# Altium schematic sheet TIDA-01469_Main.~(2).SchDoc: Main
size 431 x 279 mm; Date: Not shown in title block; ApprovedBy: Not shown in title block; CheckedBy: Not shown in title block; Author: Not shown in title block; CompanyName: Not shown in title block; DrawnBy: Nathan Siegel; Engineer: Not shown in title block; Organization: Not shown in title block; Address1: Not shown in title block; Address2: Not shown in title block; Address3: Not shown in title block; Address4: Not shown in title block; DocumentNumber: 2; Revision: Use project parameter SCH_Rev; SheetNumber: 2; SheetTotal: 4; PageSetup: Record=PageOptions¦CenterHorizontal=True¦CenterVertical=True¦PrintScale=1.00¦XCorrection=1.00¦YCorrection=1.00¦PrintKind=0¦BorderSize=5000000¦LeftOffset=0¦BottomOffset=0¦Orientation=2¦PaperLength=1000¦PaperWidth=1000¦Scale=100¦PaperSource=15¦PrintQuality=600¦MediaType=1¦DitherType=10¦PaperKind=Letter¦PrintScaleMode=1
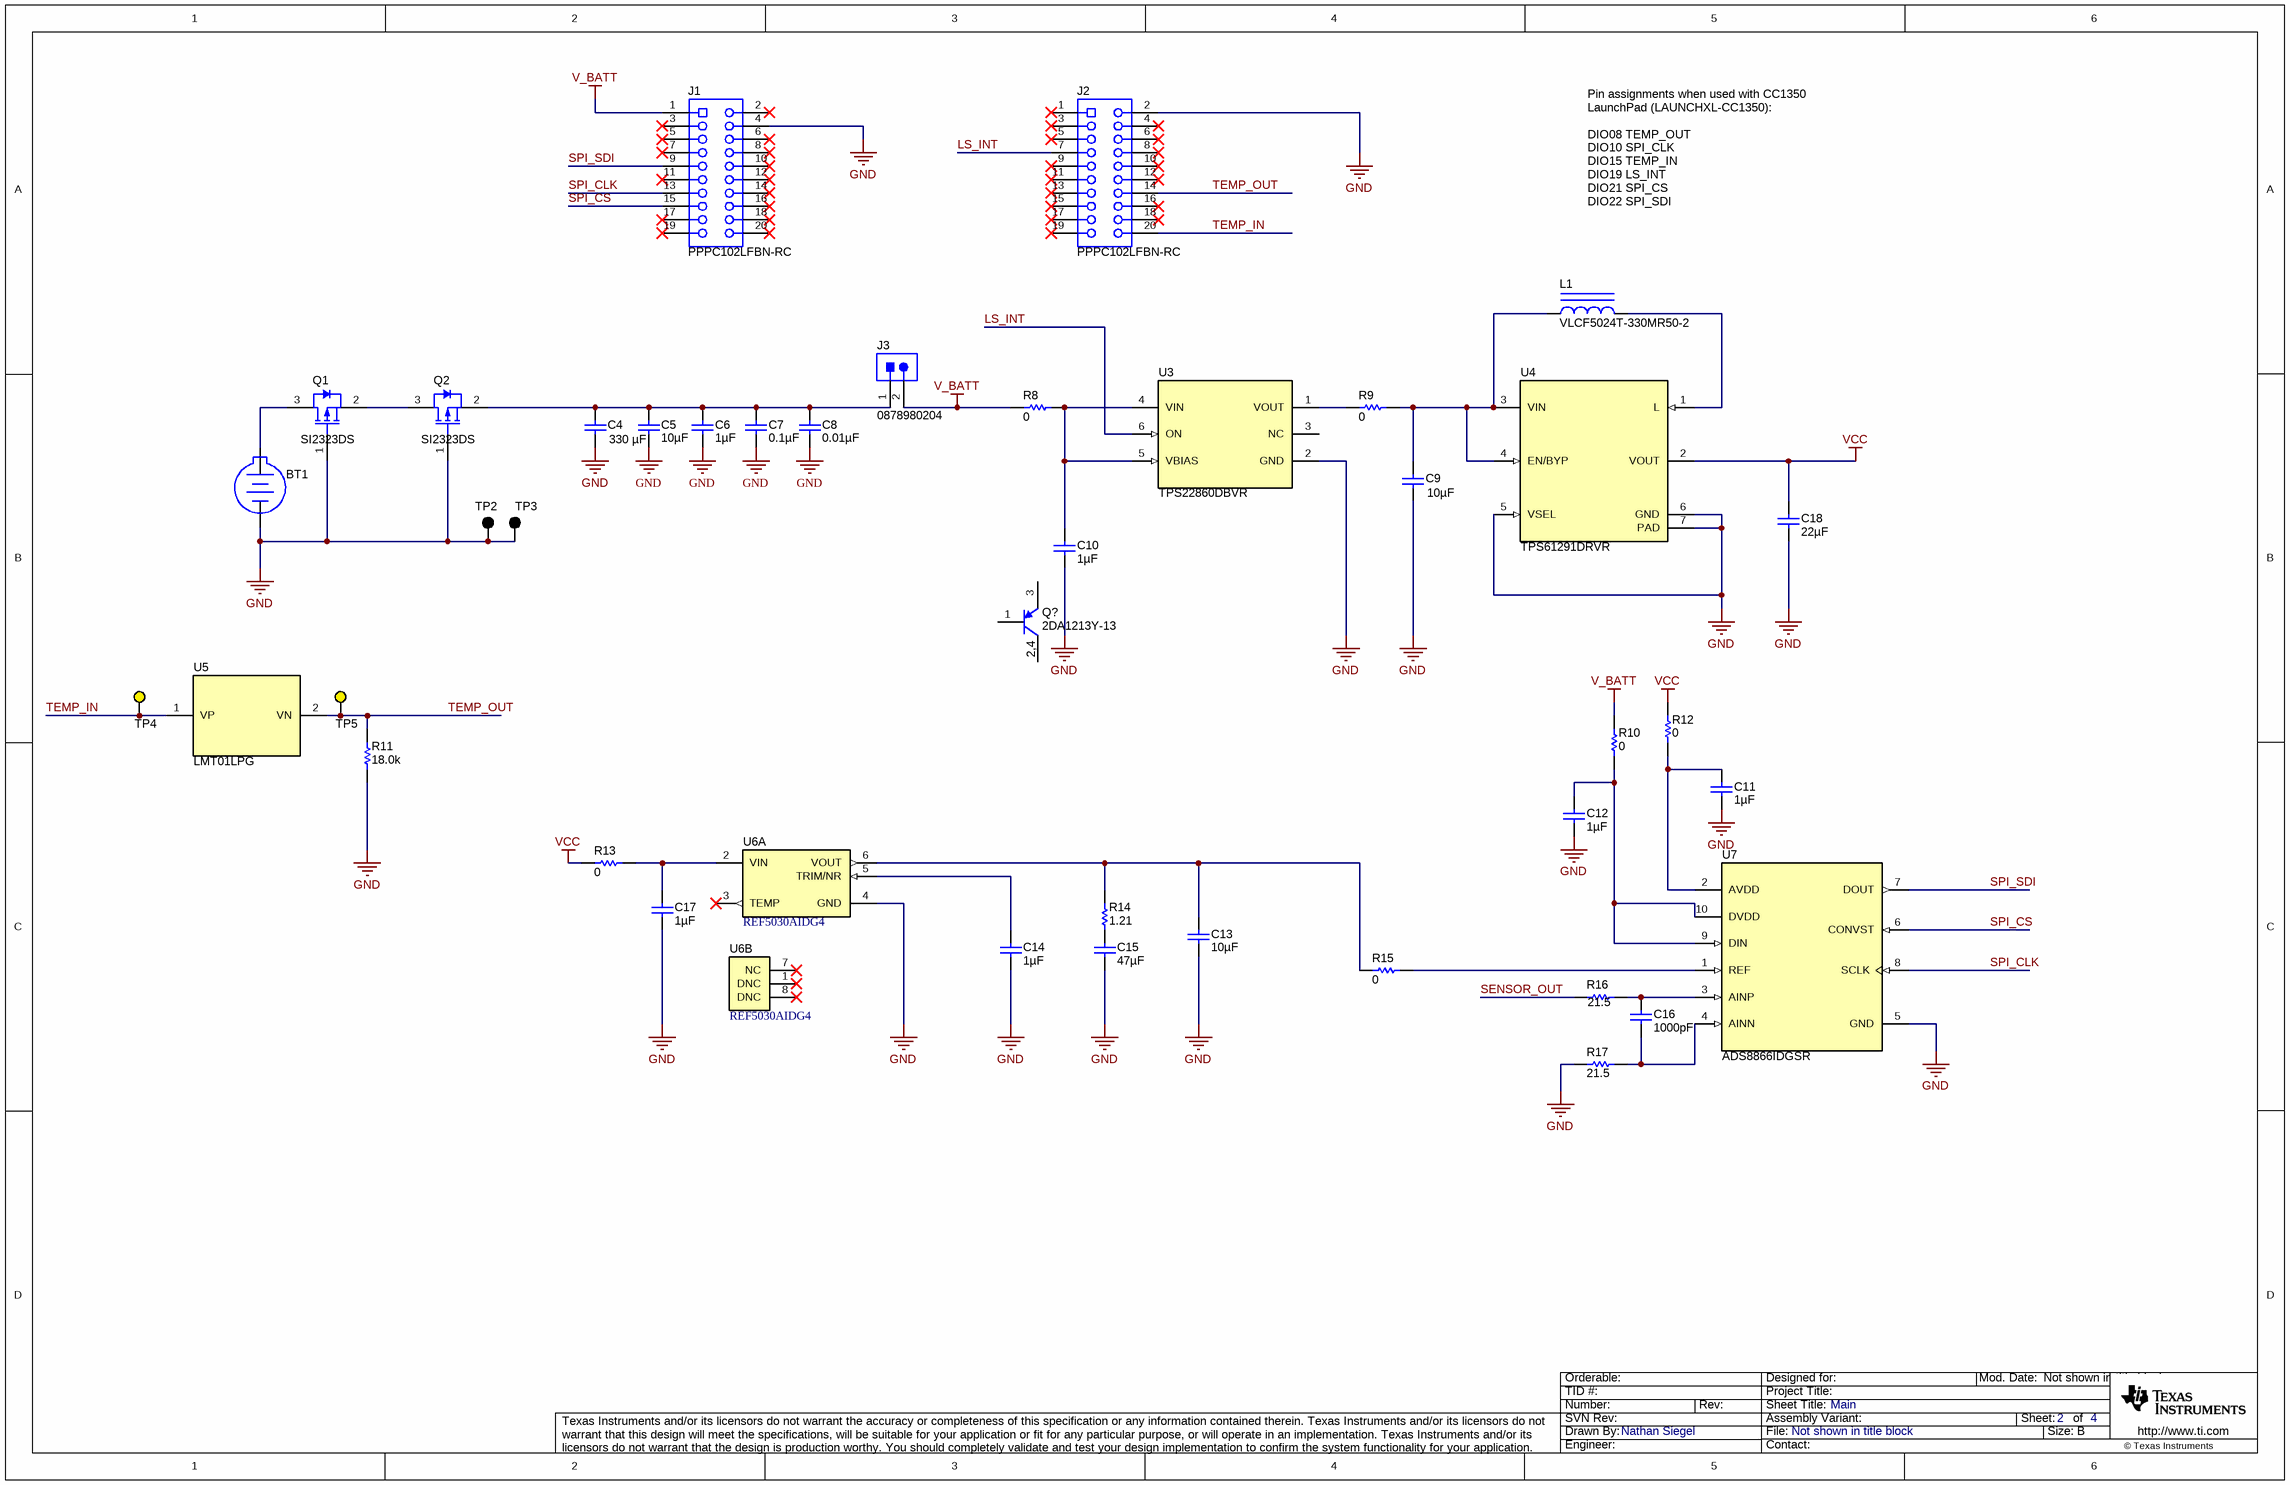
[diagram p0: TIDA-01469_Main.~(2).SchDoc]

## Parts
BT1  BS-7  [BAT_BS-7]  (value not drawn)
C4  ValueDisplayed: 330 µF  [1210]  (hidden comment: GRM32ER60G337ME05L)
C5  ValueDisplayed: 10µF  [0603]  (hidden comment: C1608X5R0J106M)
C6  ValueDisplayed: 1µF  [0603]  (hidden comment: C1608X7R1C105K)
C7  ValueDisplayed: 0.1µF  [0402]  (hidden comment: C1005X7R1H104K050BB)
C8  ValueDisplayed: 0.01µF  [0402]  (hidden comment: C1005X7R1C103K050BA)
C9  ValueDisplayed: 10µF  [0603]  (hidden comment: C0603C106M9PACTU)
C10  ValueDisplayed: 1µF  [0402]  (hidden comment: C1005X7S1A105K050BC)
C11  ValueDisplayed: 1µF  [0402]  (hidden comment: C1005X7S1A105K050BC)
C12  ValueDisplayed: 1µF  [0402]  (hidden comment: C1005X7S1A105K050BC)
C13  ValueDisplayed: 10µF  [0603]  (hidden comment: C0603C106M9PACTU)
C14  ValueDisplayed: 1µF  [0402]  (hidden comment: C1005X7S1A105K050BC)
C15  ValueDisplayed: 47µF  [0805_HV]  (hidden comment: C2012X5R1A476M125AC)
C16  ValueDisplayed: 1000pF  [0603]  (hidden comment: 06031C102JAT2A)
C17  ValueDisplayed: 1µF  [0603]  (hidden comment: 06033C105KAT2A)
C18  ValueDisplayed: 22µF  [0603S]  (hidden comment: C1608X5R0G226M080AA)
J1  PPPC102LFBN-RC  [Sullins_PPPC102LFBN-RC]
J2  PPPC102LFBN-RC  [Sullins_PPPC102LFBN-RC]
J3  0878980204  [Molex_87898-0204]
L1  VLCF5024T-330MR50-2  [VLCF5024]
Q1  SI2323DS  [SOT-23]
Q2  SI2323DS  [SOT-23]
Q?  2DA1213Y-13  [SOT-89-3]
R8  ValueDisplayed: 0  [0603]  (hidden comment: RMCF0603ZT0R00)
R9  ValueDisplayed: 0  [0603]  (hidden comment: RMCF0603ZT0R00)
R10  ValueDisplayed: 0  [0603]  (hidden comment: RMCF0603ZT0R00)
R11  ValueDisplayed: 18.0k  [0402]  (hidden comment: CRCW040218K0FKED)
R12  ValueDisplayed: 0  [0603]  (hidden comment: RMCF0603ZT0R00)
R13  ValueDisplayed: 0  [0603]  (hidden comment: RMCF0603ZT0R00)
R14  ValueDisplayed: 1.21  [0402]  (hidden comment: CRCW04021R21FKED)
R15  ValueDisplayed: 0  [0603]  (hidden comment: RMCF0603ZT0R00)
R16  ValueDisplayed: 21.5  [0402]  (hidden comment: CRCW040221R5FKED)
R17  ValueDisplayed: 21.5  [0402]  (hidden comment: CRCW040221R5FKED)
TP2  5011  [Keystone5011]  (value not drawn)
TP3  5011  [Keystone5011]  (value not drawn)
TP4  5004  [Keystone5004]  (value not drawn)
TP5  5004  [Keystone5004]  (value not drawn)
U3  TPS22860DBVR  [DBV0006A_N]
U4  TPS61291DRVR  [DRV0006A]
U5  LMT01LPG  [LPG0002A]
U6  REF5030AIDG4  [D0008A_N]  (parts A,B of 2)
U7  ADS8866IDGSR  [DGS0010A_L]

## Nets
GND: BT1.2(-) C4.2 C5.2 C6.2 C7.2 C8.2 C9.2 C10.2 C11.2 C12.2 C13.2 C14.2 C15.2 C17.2 C18.2 J1.4 J2.2 Q1.1(G) Q2.1(G) R11.1 R17.1 TP2.1 TP3.1 U3.2(GND) U4.5(VSEL) U4.6(GND) U4.7(PAD) U6.4(GND) U7.5(GND)
V_BATT: J1.1 J3.2 R8.1 R10.2
VCC: C18.1 R12.2 R13.1 U4.2(VOUT)
LS_INT: J2.7 U3.6(ON)
SENSOR_OUT: R16.1
SPI_CLK: J1.13 U7.8(SCLK)
SPI_CS: J1.15 U7.6(CONVST)
SPI_SDI: J1.9 U7.7(DOUT)
TEMP_IN: J2.20 TP4.1 U5.1(VP)
TEMP_OUT: J2.14 R11.2 TP5.1 U5.2(VN)
NetBT1_1: BT1.1(+) Q1.3(D)
NetC4_1: C4.1 C5.1 C6.1 C7.1 C8.1 J3.1 Q2.2(S)
NetC9_1: C9.1 L1.1 R9.2 U4.3(VIN) U4.4(EN/BYP)
NetC10_1: C10.1 R8.2 U3.4(VIN) U3.5(VBIAS)
NetC11_1: C11.1 R12.1 U7.2(AVDD)
NetC12_1: C12.1 R10.1 U7.9(DIN) U7.10(DVDD)
NetC13_1: C13.1 R14.2 R15.1 U6.6(VOUT)
NetC14_1: C14.1 U6.5(TRIM/NR)
NetC15_1: C15.1 R14.1
NetC16_1: C16.1 R16.2 U7.3(AINP)
NetC16_2: C16.2 R17.2 U7.4(AINN)
NetC17_1: C17.1 R13.2 U6.2(VIN)
NetL1_2: L1.2 U4.1(L)
NetQ1_2: Q1.2(S) Q2.3(D)
NetQ?_2: Q?.2(C) Q?.4(C)
NetR9_1: R9.1 U3.1(VOUT)
NetR15_2: R15.2 U7.1(REF)

Not connected (* = marked no-connect by the designer): J1 2* 3* 5* 6* 7* 8* 10* 11* 12* 14* 16* 17* 18* 19* 20*; J2 1* 3* 4* 5* 6* 8* 9* 10* 11* 12* 13* 15* 16* 17* 18* 19*; Q? 1(B) 3(E); U3 3(NC); U6 1(DNC)* 3(TEMP)* 7(NC)* 8(DNC)*

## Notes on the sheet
- Pin assignments when used with CC1350 LaunchPad (LAUNCHXL-CC1350):
  DIO08	TEMP_OUT
  DIO10	SPI_CLK
  DIO15	TEMP_IN
  DIO19	LS_INT
  DIO21	SPI_CS
  DIO22	SPI_SDI

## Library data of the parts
BT1 = BS-7: Battery Holder, CR2032, Retainer clip, TH; Manufacturer: Memory Protection Devices; SymbolCreator: a0412235
C4 = Capacitor: CAP, CERM, 330 µF, 4 V, X5R, +/- 20%, 1210; Manufacturer: Murata; Polarized: N; Value: 330 uF; U/M: EA
C5 = C1608X5R0J106M: CAP, CERM, 10 µF, 6.3 V, +/- 20%, X5R, 0603; Manufacturer: TDK; Polarized: N; CompType: Capacitor; Value: 10uF; U/M: EA; Cap_F: 0.00001; Tolerance_%: 20; ESR_ohm: 0.005; Value1: 0.005 ohm; VDC_V: 6.3; Value2: 6.3V; IRMS_A: 1.9; TaMin_C: -25; TaMax_C: 85; AEC Category: Q200
C6 = C1608X7R1C105K: CAP, CERM, 1 µF, 16 V, +/- 10%, X7R, 0603; Manufacturer: TDK; Polarized: N; CompType: Capacitor; Value: 1uF; U/M: EA; Cap_F: 0.000001; Tolerance_%: 10; ESR_ohm: 0.0057; Value1: 0.0057 ohm; VDC_V: 16; Value2: 16V; TaMin_C: -55; TaMax_C: 125; AEC Category: Q200
C7 = C1005X7R1H104K050BB: CAP, CERM, 0.1 µF, 50 V, +/- 10%, X7R, 0402; Manufacturer: TDK; Polarized: N; CompType: Capacitor; Value: 0.1uF; U/M: EA; Cap_F: 0.0000001; Tolerance_%: 10; Value1: Unknown; VDC_V: 50; Value2: 50V; TaMin_C: -55; TaMax_C: 125; AEC Category: Q200
C8 = C1005X7R1C103K050BA: CAP, CERM, 0.01 µF, 16 V, +/- 10%, X7R, 0402; Manufacturer: TDK; Polarized: N; CompType: Capacitor; Value: 0.01uF; U/M: EA; Cap_F: 0.00000001; Tolerance_%: 10; ESR_ohm: 0.0623; Value1: 0.0623 ohm; VDC_V: 16; Value2: 16V; TaMin_C: -55; TaMax_C: 125; AEC Category: Q200
C9 C13 = C0603C106M9PACTU: CAP, CERM, 10 µF, 6.3 V, +/- 20%, X5R, 0603; Manufacturer: Kemet; Polarized: N; CompType: Capacitor; Value: 10uF; U/M: EA; Cap_F: 0.00001; Tolerance_%: 20; ESR_ohm: 0.004; Value1: 0.004 ohm; VDC_V: 6.3; Value2: 6.3V; IRMS_A: 8.9; TaMin_C: -55; TaMax_C: 85; SizeArea_mm2: 1.28; SizeAreaWB_mm2: 4.68; SizeX_mm: 1.6; SizeY_mm: 0.8; SizeZ_mm: 1; AEC Category: Q200
C10-C12 C14 = C1005X7S1A105K050BC: CAP, CERM, 1 µF, 10 V, +/- 10%, X7S, 0402; Manufacturer: TDK; Polarized: N; CompType: Capacitor; Value: 1uF; U/M: EA; Cap_F: 0.000001; Tolerance_%: 10; ESR_ohm: 0.011416; Value1: 0.011416 ohm; Value2: 10V; IRMS_A: 1.483; TaMin_C: -55; TaMax_C: 125; SizeArea_mm2: 0.5; SizeAreaWB_mm2: 3; SizeX_mm: 1; SizeZ_mm: 0.6; AEC Category: Q200
C15 = C2012X5R1A476M125AC: CAP, CERM, 47 µF, 10 V, +/- 20%, X5R, 0805; Manufacturer: TDK; Polarized: N; CompType: Capacitor; Value: 47uF; U/M: EA; Cap_F: 0.000047; Tolerance_%: 20; ESR_ohm: 0.00294; Value1: 0.00294 ohm; VDC_V: 10; Value2: 10V; IRMS_A: 3.80451; TaMin_C: -55; TaMax_C: 85; Cap_Case: 0805; SizeArea_mm2: 2.5; SizeAreaWB_mm2: 6.75; SizeX_mm: 2; SizeY_mm: 1.25; SizeZ_mm: 1.45; AEC Category: Q200
C16 = 06031C102JAT2A: CAP, CERM, 1000 pF, 100 V, +/- 5%, X7R, 0603; Manufacturer: AVX; Polarized: N; CompType: Capacitor; Value: 1000pF; U/M: EA; Cap_F: 0.000000001; Tolerance_%: 5; ESR_ohm: 0.276; Value1: 0.276 ohm; VDC_V: 100; Value2: 100V; TaMin_C: -55; TaMax_C: 125; SizeArea_mm2: 1.28; SizeAreaWB_mm2: 4.68; SizeX_mm: 1.6; SizeY_mm: 0.8; SizeZ_mm: 1; AEC Category: Q200; Green_Lifecycle: Active; Green_REACh: Passed
C17 = 06033C105KAT2A: CAP, CERM, 1 µF, 25 V, +/- 10%, X7R, 0603; Manufacturer: AVX; Polarized: N; CompType: Capacitor; Value: 1uF; U/M: EA; Cap_F: 0.000001; Tolerance_%: 10; Value1: Unknown; VDC_V: 25; Value2: 25V; TaMin_C: -55; TaMax_C: 125; SizeArea_mm2: 1.28; SizeAreaWB_mm2: 4.68; SizeX_mm: 1.6; SizeY_mm: 0.8; SizeZ_mm: 1; AEC Category: Q200
C18 = C1608X5R0G226M080AA: CAP, CERM, 22 µF, 4 V, +/- 20%, X5R, 0603; Manufacturer: TDK; Polarized: N; CompType: Capacitor; Value: 22uF; U/M: EA; Cap_F: 0.000022; Tolerance_%: 20; Value1: Unknown; VDC_V: 4; Value2: 4V; TaMin_C: -55; TaMax_C: 85; Cap_Case: 0603; SizeArea_mm2: 1.28; SizeAreaWB_mm2: 4.68; SizeX_mm: 1.6; SizeY_mm: 0.8; SizeZ_mm: 1; AEC Category: Q200; Green_Lifecycle: Active; Green_REACh: Passed
J1 J2 = PPPC102LFBN-RC: Receptacle, 100mil, 10x2, Gold, TH; Manufacturer: Sullins Connector Solutions; SymbolCreator: a0412235
J3 = 0878980204: Header, 2.54 mm, 2x1, Gold, R/A, SMT; Manufacturer: Molex; SymbolCreator: a0412235; Pitch_mm: 2.54; Gender: Male; Shrouded: N; Row_Count: 1
L1 = VLCF5024T-330MR50-2: Inductor, Shielded, Ferrite, 0.5 A, 0.275 ohm, SMD; Manufacturer: TDK; Imax_A: 0.5; Irms: 1.24A @ 40C rise; Isat: 0.5A @ 30% inductance drop; DCR_ohm: 0.275; Value2: 0.5A; SizeAreaWB_mm2: 52.56; SizeArea_mm2: 27.56; SizeX_mm: 5.3; SizeY_mm: 5.2; SizeZ_mm: 2.8; AEC Category: Q200
Q1 Q2 = SI2323DS: MOSFET, P-CH, -20 V, -3.7 A, SOT-23; Manufacturer: Vishay-Siliconix; Alternate Manufacturer: None; U/M: EA; ChType: P; Value: -20V; Value1: 0.031 ohm; Rdson45_ohm: 0.031; Value2: 12.5 nC; QgTyp_nC: 12.5; Vgs_V: -8; SizeAreaWB_mm2: 14; SizeArea_mm2: 7.5; SizeX_mm: 2.5; SizeY_mm: 3; SizeZ_mm: 1.1; AEC Category: Q101
Q? = 2DA1213Y-13, Diodes Inc.: Transistor, PNP, -50 V, -2 A, AEC-Q101, SOT-89; CompType: BJT; PNP: 1; NPN: 0; Vcesat1_V: -0.5; Value: -50 V; Value1: -2 A; HfeMax: 240; TaMin_C: -55; TaMax_C: 150; SizeAreaWB_mm2: 28.05; SizeArea_mm2: 18.45; SizeX_mm: 4.1; SizeY_mm: 4.5; SizeZ_mm: 1.5; U/M: EA; AEC Category: Q101; AEC Qualified: Y
R8-R10 R12 R13 R15 = RMCF0603ZT0R00: RES, 0, 1%, 0.1 W, AEC-Q200 Grade 0, 0603; Manufacturer: Stackpole Electronics Inc; CompType: Resistor; Value: 0; Tolerance_%: 1; Power_W: 0.1; Value2: 0.1W; TempCo: ppm/C; SizeArea_mm2: 1.28; SizeX_mm: 1.6; SizeY_mm: 0.8; U/M: EA; AEC Category: Q200; AEC Qualified: Y; Green_Lifecycle: Active; Green_REACh: Passed
R11 = CRCW040218K0FKED: RES, 18.0 k, 1%, 0.063 W, AEC-Q200 Grade 0, 0402; Manufacturer: Vishay-Dale; CompType: Resistor; Value: 18.0k; Res_ohm: 18000; Value_Code: 18k0; Tolerance_%: 1; Power_W: 0.063; Value2: 0.063W; VDC_V: 50; TempCo: 100 ppm/C; SizeArea_mm2: 0.5; SizeZ_mm: 0.6; U/M: EA; AEC Category: Q200; AEC Qualified: Y; AEC Grade: 0
R14 = CRCW04021R21FKED: RES, 1.21, 1%, 0.063 W, 0402; Manufacturer: Vishay-Dale; CompType: Resistor; Value: 1.21; Value_Code: 1R21; Tolerance_%: 1; Power_W: 0.063; Value2: 0.063W; VDC_V: 50; TempCo: 100 ppm/C; SizeArea_mm2: 0.5; SizeZ_mm: 0.6; EIA_Code: E96; U/M: EA; AEC Category: Q200
R16 R17 = CRCW040221R5FKED: RES, 21.5, 1%, 0.063 W, 0402; Manufacturer: Vishay-Dale; CompType: Resistor; Value: 21.5; Value_Code: 21R5; Tolerance_%: 1; Power_W: 0.063; Value2: 0.063W; VDC_V: 50; TempCo: 100 ppm/C; SizeArea_mm2: 0.5; SizeZ_mm: 0.6; EIA_Code: E96; U/M: EA; AEC Category: Q200
TP2 TP3 = 5011: Test Point, Multipurpose, Black, TH; Manufacturer: Keystone; CompType: Test Point Loop; ContactFinish: Silver
TP4 TP5 = 5004: Test Point, Miniature, Yellow, TH; Manufacturer: Keystone; CompType: Test Point Loop; ContactFinish: Silver
U3 = TPS22860DBVR: TPS22860 Ultra-low leakage load switch, DBV0006A (SOT-23-6); Manufacturer: Texas Instruments; SymbolCreator: Altium; SizeArea_mm2: 8.12; SizeAreaWB_mm2: 14.82; SizeX_mm: 2.8; SizeY_mm: 2.9; SizeZ_mm: 1.45; CompType: IC; U/M: EA
U4 = TPS61291DRVR: LOW Iq BOOST CONVERTER WITH BYPASS OPERATION, DRV0006A (WSON-6); Alternate PartNumber: TPS61291DRVT; Manufacturer: Texas Instruments; SymbolCreator: a0411947; SizeArea_mm2: 4; SizeAreaWB_mm2: 9; SizeX_mm: 2; SizeZ_mm: 0.8; CompType: IC; U/M: EA
U5 = LMT01LPG: 0.5degC Accurate 2-pin Temperature Sensor with a Pulse Train Interface, LPG0002A (TO-92-2); Manufacturer: Texas Instruments; SymbolCreator: Altium; SizeArea_mm2: 12.6; SizeAreaWB_mm2: 20.75; SizeX_mm: 4; SizeY_mm: 3.15; SizeZ_mm: 5.05; CompType: IC; U/M: EA
U6 = REF5030AIDG4: Low Noise, Very Low Drift, Precision Voltage Reference, -40 to 125 degC, 8-pin SOIC (D), Green (RoHS & no Sb/Br); Manufacturer: Texas Instruments; Alternate PartNumber: Equivalent; Initial Accuracy @ 25/deg C(%): 0.05; Iout/Iz(Max)(mA): 10; Iq(Max)(uA): 1000; Rating: Catalog; SubFamily: Series Voltage Reference; Temp Coeff(Max)(ppm/ degree C): 3; VI(Max)(V): 18; VI(Min)(V): 3.2
U7 = ADS8866IDGSR: 16-Bit, 100-kSPS, Serial Interface, microPower, Miniature, Single-Ended Input, SAR Analog-to-Digital, DGS0010A (VSSOP-10); Manufacturer: Texas Instruments; SymbolCreator: Altium; SizeArea_mm2: 14.7; SizeAreaWB_mm2: 23.6; SizeX_mm: 4.9; SizeY_mm: 3; SizeZ_mm: 1.1; CompType: IC; U/M: EA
